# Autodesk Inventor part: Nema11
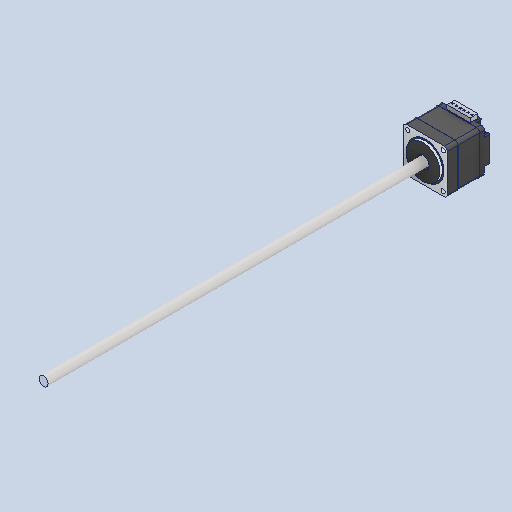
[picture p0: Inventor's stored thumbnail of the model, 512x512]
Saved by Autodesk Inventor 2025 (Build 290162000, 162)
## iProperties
Created: 2019-06
Part Number: Nema11
Material: Generico
Document SubType Name: Modeling
Designer: Ryzen5700u
Density: 1 g/cm^3
Appearance: Default
Author: Ryzen5700u
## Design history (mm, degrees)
feature "Solido1"
node "Solido2"
